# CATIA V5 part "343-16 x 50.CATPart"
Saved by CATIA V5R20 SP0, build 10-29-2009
Part number: 343-16 x 50
Definition: NONE
Nomenclature: 343-16 x 50
Source: Unknown
Description: 343-16 x 50
Bounding box of the stored display mesh (mm): x 0 to 50, y -13 to 13, z -13 to 13
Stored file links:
  C:\Users\Utente\Desktop\IO LAVORO\3D X SITO CF\X SITO\343-348\343-16 x 50.CATPart
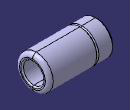
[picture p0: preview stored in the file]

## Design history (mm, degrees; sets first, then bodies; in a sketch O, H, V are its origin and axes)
Body1 "343-16 x 50" (main body)
  Solid1: solid without history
